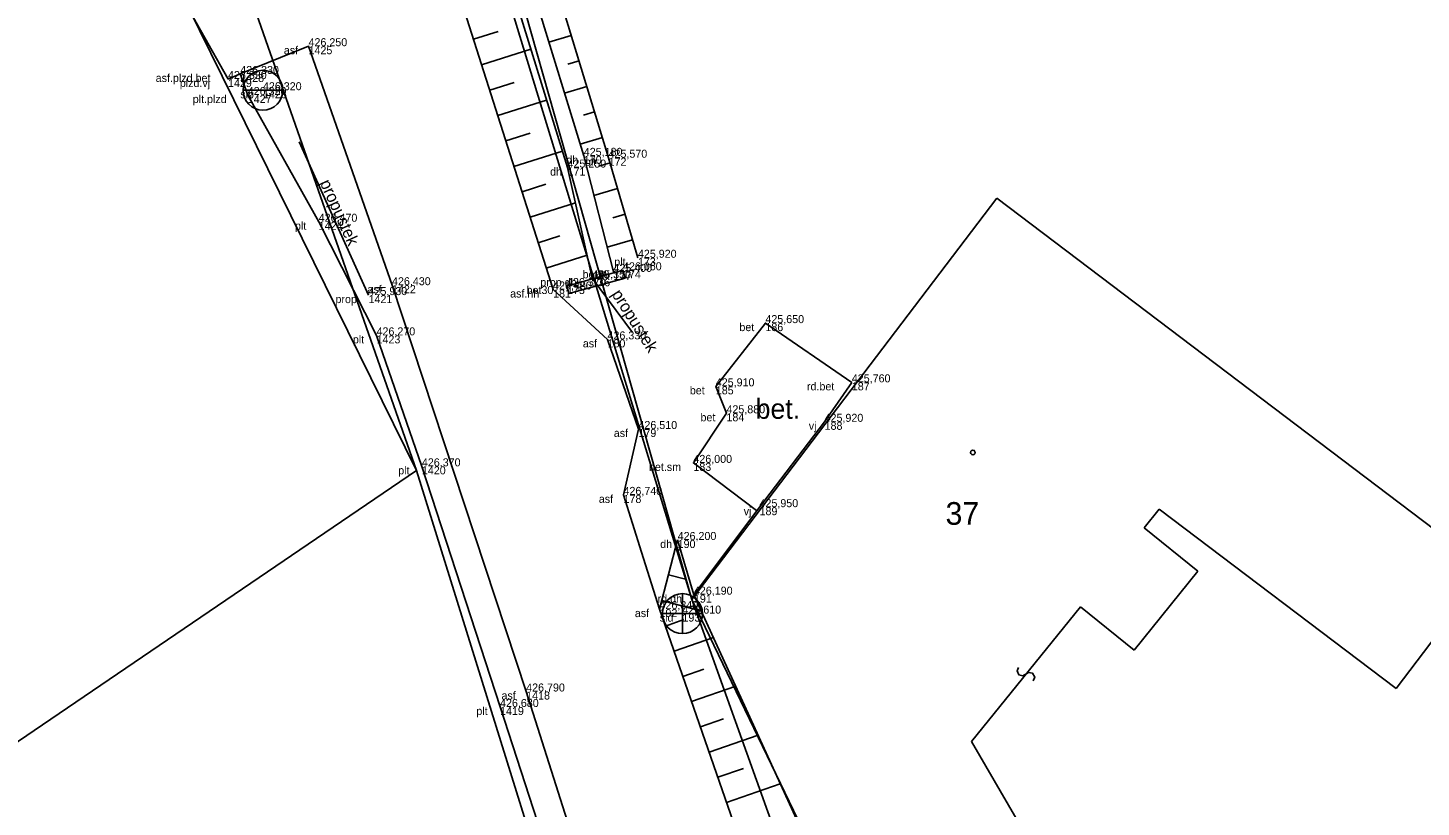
# Model space of a CAD drawing. Extents: x -747792 to -745414, y -1093712 to -1091463.
# Drawn here: x -746629.9 to -746577.7, y -1092879.6 to -1092850.4 of the extents above; entities that cross this region are included whole.
import ezdxf

# ---------------------------------------------------------------- set-up
doc = ezdxf.new("R2010")
doc.units = 0
for name, color, linetype in [('Hladina', 7, 'Continuous'), ('Koleje_dopravní prvky', 7, 'Continuous'), ('Kultury', 7, 'Continuous'), ('Nezařazené objekty', 7, 'Continuous'), ('Nivelační značky_hrany', 7, 'Continuous'), ('Ploty_opěrné zdi', 7, 'Continuous'), ('Popisy objektů_povrchů', 7, 'Continuous'), ('Pracovní_bod PPBP', 7, 'Continuous'), ('Pracovní_bod PPBP - výška', 7, 'Continuous'), ('Pracovní_bod ZPBP', 7, 'Continuous'), ('Pracovní_bod ZPBP - číslo', 7, 'Continuous'), ('Rozhraní ploch', 7, 'Continuous'), ('Stromy_porost', 7, 'Continuous'), ('Výškopis', 7, 'Continuous'), ('Čísla popisná_parcelní', 7, 'Continuous')]:
    doc.layers.add(name, color=color, linetype=linetype)

msp = doc.modelspace()

# ---------------------------------------------------------------- linework, layer by layer
at = {"layer": 'Hladina'}
for p, q in [((-746619.38, -1092851.1), (-746619.38, -1092851.1)), ((-746621.94, -1092852.14), (-746621.94, -1092852.14)), ((-746622.4, -1092852.33), (-746622.4, -1092852.33)), ((-746621.09, -1092852.75), (-746621.09, -1092852.75)), ((-746621.66, -1092852.93), (-746621.66, -1092852.93)), ((-746609.06, -1092855.21), (-746609.06, -1092855.21)), ((-746608.13, -1092855.28), (-746608.13, -1092855.28)), ((-746609.67, -1092855.65), (-746609.67, -1092855.65)), ((-746619, -1092857.68), (-746619, -1092857.68)), ((-746607.03, -1092859.03), (-746607.03, -1092859.03)), ((-746607.95, -1092859.56), (-746607.95, -1092859.56)), ((-746607.59, -1092859.5), (-746607.59, -1092859.5)), ((-746616.25, -1092860.06), (-746616.25, -1092860.06)), ((-746609.69, -1092860.09), (-746609.69, -1092860.09)), ((-746608.74, -1092859.8), (-746608.74, -1092859.8)), ((-746617.13, -1092860.43), (-746617.13, -1092860.43)), ((-746610.21, -1092860.22), (-746610.21, -1092860.22)), ((-746602.25, -1092861.48), (-746602.25, -1092861.48)), ((-746616.83, -1092861.94), (-746616.83, -1092861.94)), ((-746608.17, -1092862.09), (-746608.17, -1092862.09)), ((-746599.01, -1092863.7), (-746599.01, -1092863.7)), ((-746604.11, -1092863.85), (-746604.11, -1092863.85)), ((-746603.71, -1092864.86), (-746603.71, -1092864.86)), ((-746600.03, -1092865.18), (-746600.03, -1092865.18)), ((-746607.01, -1092865.45), (-746607.01, -1092865.45)), ((-746615.13, -1092866.85), (-746615.13, -1092866.85)), ((-746604.95, -1092866.72), (-746604.95, -1092866.72)), ((-746607.57, -1092867.92), (-746607.57, -1092867.92)), ((-746602.47, -1092868.38), (-746602.47, -1092868.38)), ((-746605.54, -1092869.61), (-746605.54, -1092869.61)), ((-746604.93, -1092871.66), (-746604.93, -1092871.66)), ((-746606.22, -1092872.2), (-746606.22, -1092872.2)), ((-746605.36, -1092872.37), (-746605.36, -1092872.37)), ((-746611.22, -1092875.29), (-746611.22, -1092875.29)), ((-746612.2, -1092875.87), (-746612.2, -1092875.87))]:
    msp.add_line(p, q, dxfattribs=at)
at = {"layer": 'Kultury'}
for points in [[(-746587.49, -1092868.45), (-746588.05, -1092869.15)], [(-746578.6, -1092875.18), (-746587.49, -1092868.45)], [(-746586.03, -1092870.78), (-746588.05, -1092869.15)], [(-746588.42, -1092873.74), (-746586.03, -1092870.78)], [(-746590.44, -1092872.11), (-746594.52, -1092877.17)], [(-746590.44, -1092872.11), (-746588.42, -1092873.74)], [(-746578.6, -1092875.18), (-746576.79, -1092872.79)], [(-746592.204, -1092874.895), (-746592.149, -1092874.747), (-746592.232, -1092874.603), (-746592.381, -1092874.572), (-746592.597, -1092874.706), (-746592.744, -1092874.665), (-746592.813, -1092874.519), (-746592.756, -1092874.385)], [(-746580.37, -1092901.51), (-746594.52, -1092877.17)]]:
    msp.add_lwpolyline(points, dxfattribs=at)
at = {"layer": 'Nezařazené objekty'}
for points in [[(-746615.54, -1092831.62), (-746612.94, -1092839.49), (-746608.13, -1092855.28), (-746607.03, -1092859.03)], [(-746621.66, -1092852.93), (-746621.94, -1092852.14), (-746622.4, -1092852.33)], [(-746605.5, -1092896.5), (-746612.2, -1092875.87), (-746615.13, -1092866.85), (-746616.83, -1092861.94), (-746619, -1092857.68), (-746621.66, -1092852.93)]]:
    msp.add_lwpolyline(points, dxfattribs=at)
at = {"layer": 'Nivelační značky_hrany'}
for points in [[(-746618.84, -1092832.7), (-746614.69, -1092846.13), (-746610.21, -1092860.22)], [(-746604.94, -1092923.82), (-746603.73, -1092922.94), (-746602.98, -1092921.58), (-746602.37, -1092919.14), (-746601.93, -1092916.74), (-746601.75, -1092914.6), (-746601.83, -1092911.07), (-746602.53, -1092905.39), (-746603.47, -1092900.25), (-746604.79, -1092895.49), (-746611.22, -1092875.29), (-746616.25, -1092860.06), (-746619.38, -1092851.1), (-746621.94, -1092852.14)], [(-746609.69, -1092860.09), (-746607.59, -1092859.5), (-746607.51, -1092859.789), (-746609.62, -1092860.37), (-746609.69, -1092860.09)], [(-746610.21, -1092860.22), (-746608.17, -1092862.09), (-746607.01, -1092865.45), (-746607.57, -1092867.92), (-746606.89, -1092870.07)], [(-746599.01, -1092863.7), (-746602.25, -1092861.48), (-746604.11, -1092863.85), (-746603.71, -1092864.86), (-746604.95, -1092866.72), (-746602.58, -1092868.51)], [(-746606.89, -1092870.07), (-746606.22, -1092872.2), (-746601.94, -1092884.53), (-746599.63, -1092891.7), (-746597.35, -1092899.83), (-746595.6, -1092905.67), (-746593.1, -1092909.17), (-746589.17, -1092912.29), (-746583.92, -1092914.8), (-746581.66, -1092915.56), (-746580.14, -1092915.86), (-746577.29, -1092915.71), (-746575.17, -1092914.86), (-746572.81, -1092912.41), (-746569.47, -1092912.97), (-746567.46, -1092919.83), (-746565.22, -1092924.53), (-746564.79, -1092924.01)]]:
    msp.add_lwpolyline(points, dxfattribs=at)
at = {"layer": 'Ploty_opěrné zdi'}
msp.add_lwpolyline([(-746594.47, -1092866.245), (-746594.42, -1092866.255), (-746594.395, -1092866.3), (-746594.385, -1092866.33), (-746594.395, -1092866.375), (-746594.435, -1092866.41), (-746594.47, -1092866.415), (-746594.515, -1092866.4), (-746594.545, -1092866.37), (-746594.555, -1092866.33), (-746594.545, -1092866.285), (-746594.505, -1092866.25)], close=True, dxfattribs=at)
at = {"layer": 'Popisy objektů_povrchů'}
for points in [[(-746599.01, -1092863.7), (-746600.03, -1092865.18)], [(-746602.47, -1092868.38), (-746600.03, -1092865.18)], [(-746602.47, -1092868.38), (-746604.93, -1092871.66), (-746599.59, -1092883.35), (-746595.82, -1092889.24)]]:
    msp.add_lwpolyline(points, dxfattribs=at)
at = {"layer": 'Pracovní_bod PPBP'}
for points in [[(-746607.95, -1092859.56), (-746609.06, -1092855.21), (-746612.68, -1092843.4), (-746616.204, -1092831.845)], [(-746617.084, -1092832.121), (-746613.3, -1092843.93), (-746609.67, -1092855.65), (-746608.74, -1092859.8)], [(-746613.192, -1092850.841), (-746612.267, -1092850.547)], [(-746609.527, -1092850.693), (-746610.366, -1092850.949)], [(-746612.889, -1092851.794), (-746611.046, -1092851.208)], [(-746609.236, -1092851.65), (-746609.654, -1092851.777)], [(-746612.586, -1092852.747), (-746611.668, -1092852.455)], [(-746608.944, -1092852.607), (-746609.78, -1092852.861)], [(-746612.283, -1092853.7), (-746610.454, -1092853.118)], [(-746608.653, -1092853.563), (-746609.07, -1092853.69)], [(-746611.98, -1092854.653), (-746611.069, -1092854.363)], [(-746608.362, -1092854.52), (-746609.194, -1092854.773)], [(-746611.677, -1092855.606), (-746609.862, -1092855.029)], [(-746608.072, -1092855.477), (-746608.5, -1092855.602)], [(-746611.374, -1092856.559), (-746610.484, -1092856.276)], [(-746607.791, -1092856.437), (-746608.68, -1092856.698)], [(-746611.071, -1092857.512), (-746609.374, -1092856.972)], [(-746607.509, -1092857.396), (-746607.971, -1092857.532)], [(-746610.768, -1092858.465), (-746609.961, -1092858.208)], [(-746607.228, -1092858.356), (-746608.186, -1092858.637)], [(-746610.465, -1092859.418), (-746608.935, -1092858.931)], [(-746606.22, -1092872.2), (-746605.54, -1092869.61)], [(-746605.629, -1092869.949), (-746605.449, -1092869.996)], [(-746604.93, -1092871.66), (-746605.54, -1092869.61)], [(-746605.883, -1092870.916), (-746605.252, -1092871.082)], [(-746606.137, -1092871.883), (-746604.65, -1092872.274)], [(-746605.999, -1092872.835), (-746605.306, -1092872.595)], [(-746605.672, -1092873.78), (-746604.196, -1092873.268)], [(-746605.344, -1092874.725), (-746604.561, -1092874.453)], [(-746605.016, -1092875.669), (-746603.361, -1092875.095)], [(-746604.688, -1092876.614), (-746603.816, -1092876.311)], [(-746604.36, -1092877.559), (-746602.526, -1092876.922)], [(-746604.032, -1092878.503), (-746603.07, -1092878.17)], [(-746603.704, -1092879.448), (-746601.691, -1092878.75)]]:
    msp.add_lwpolyline(points, dxfattribs=at)
at = {"layer": 'Pracovní_bod PPBP - výška'}
msp.add_lwpolyline([(-746622.4, -1092852.33), (-746624.3, -1092848.94)], dxfattribs=at)
at = {"layer": 'Pracovní_bod ZPBP'}
for points in [[(-746617.13, -1092860.43), (-746619.73, -1092854.69)], [(-746608.74, -1092859.8), (-746607.23, -1092861.83)]]:
    msp.add_lwpolyline(points, dxfattribs=at)
at = {"layer": 'Stromy_porost'}
for points in [[(-746605.01, -1092871.84), (-746616.4, -1092831.67)], [(-746624.42, -1092841.06), (-746615.33, -1092867)], [(-746615.33, -1092867), (-746627.76, -1092841.79)], [(-746613.27, -1092844.77), (-746605.01, -1092871.84)], [(-746593.57, -1092856.8), (-746605.01, -1092871.84)], [(-746575.86, -1092870.2), (-746593.57, -1092856.8)], [(-746663.9, -1092900.02), (-746615.33, -1092867)], [(-746615.33, -1092867), (-746604.26, -1092902.58)], [(-746605.01, -1092871.84), (-746600.2, -1092881.82)], [(-746605.01, -1092871.84), (-746593.18, -1092904.87)]]:
    msp.add_lwpolyline(points, dxfattribs=at)
at = {"layer": 'Čísla popisná_parcelní'}
for p, q in [((-746620.343, -1092852.75), (-746621.838, -1092852.75)), ((-746605.359, -1092871.622), (-746605.36, -1092873.117)), ((-746606.112, -1092872.364), (-746604.612, -1092872.369))]:
    msp.add_line(p, q, dxfattribs=at)
msp.add_circle((-746605.36, -1092872.37), 0.75, dxfattribs=at)
for start, end in [(0, 180), (180, 0)]:
    msp.add_arc((-746621.09, -1092852.75), 0.747, start, end, dxfattribs=at)

# ---------------------------------------------------------------- texts
at = {"layer": 'Koleje_dopravní prvky'}
msp.add_text('37', height=0.85, dxfattribs=at).set_placement((-746595.496, -1092869.04))
at = {"layer": 'Pracovní_bod ZPBP - číslo'}
for s, height, rotation, p in [('propustek', 0.45, 294.4001, (-746618.969, -1092856.215)), ('propustek', 0.45, 302.2556, (-746608.034, -1092860.391)), ('bet.', 0.75, 0.0053, (-746602.617, -1092865.067))]:
    msp.add_text(s, height=height, rotation=rotation, dxfattribs=at).set_placement(p)
at = {"layer": 'Rozhraní ploch'}
for s, p in [(' asf', (-746620.417, -1092851.4)), ('1425', (-746619.38, -1092851.4)), (' asf.plzd.bet', (-746625.223, -1092852.44)), ('1428', (-746621.94, -1092852.44)), (' plzd.vj', (-746624.318, -1092852.63)), ('1429', (-746622.4, -1092852.63)), (' slb', (-746622.051, -1092853.05)), ('1426', (-746621.09, -1092853.05)), (' plt.plzd', (-746623.833, -1092853.23)), ('1427', (-746621.66, -1092853.23)), (' dh', (-746609.825, -1092855.51)), ('170', (-746609.06, -1092855.51)), (' plt', (-746609.129, -1092855.58)), ('172', (-746608.13, -1092855.58)), (' dh', (-746610.435, -1092855.95)), ('171', (-746609.67, -1092855.95)), (' plt', (-746619.999, -1092857.98)), ('1424', (-746619, -1092857.98)), (' plt', (-746608.029, -1092859.33)), ('173', (-746607.03, -1092859.33)), (' bet30', (-746609.217, -1092859.8)), (' dh', (-746608.715, -1092859.86)), ('177', (-746607.95, -1092859.86)), ('174', (-746607.59, -1092859.8)), (' asf', (-746617.287, -1092860.36)), ('1422', (-746616.25, -1092860.36)), (' bet30', (-746611.317, -1092860.39)), (' prop.dh', (-746610.802, -1092860.1)), ('175', (-746609.69, -1092860.39)), ('176', (-746608.74, -1092860.1)), (' prop', (-746618.481, -1092860.73)), ('1421', (-746617.13, -1092860.73)), (' asf.hh', (-746611.932, -1092860.52)), ('181', (-746610.21, -1092860.52)), (' bet', (-746603.336, -1092861.78)), ('186', (-746602.25, -1092861.78)), (' plt', (-746617.829, -1092862.24)), ('1423', (-746616.83, -1092862.24)), (' asf', (-746609.207, -1092862.39)), ('180', (-746608.17, -1092862.39)), (' rd.bet', (-746600.803, -1092864)), ('187', (-746599.01, -1092864)), (' bet', (-746605.196, -1092864.15)), ('185', (-746604.11, -1092864.15)), (' bet', (-746604.796, -1092865.16)), ('184', (-746603.71, -1092865.16)), (' vj', (-746600.734, -1092865.48)), ('188', (-746600.03, -1092865.48)), (' asf', (-746608.047, -1092865.75)), ('179', (-746607.01, -1092865.75)), (' plt', (-746616.129, -1092867.15)), ('1420', (-746615.13, -1092867.15)), (' bet.sm', (-746606.726, -1092867.02)), ('183', (-746604.95, -1092867.02)), (' asf', (-746608.607, -1092868.22)), ('178', (-746607.57, -1092868.22)), (' vj', (-746603.174, -1092868.68)), ('189', (-746602.47, -1092868.68)), (' dh', (-746606.305, -1092869.91)), ('190', (-746605.54, -1092869.91)), (' rd.dh', (-746606.401, -1092871.96)), ('191', (-746604.93, -1092871.96)), (' asf', (-746607.257, -1092872.5)), (' sld', (-746606.321, -1092872.67)), ('192', (-746606.22, -1092872.5)), ('193', (-746605.36, -1092872.67)), (' asf', (-746612.257, -1092875.59)), ('1418', (-746611.22, -1092875.59)), (' plt', (-746613.199, -1092876.17)), ('1419', (-746612.2, -1092876.17))]:
    msp.add_text(s, height=0.3, dxfattribs=at).set_placement(p)
at = {"layer": 'Výškopis'}
for s, p in [('426,250', (-746619.38, -1092851.1)), ('426,330', (-746622.4, -1092852.33)), ('426,330', (-746621.94, -1092852.14)), ('426,320', (-746621.66, -1092852.93)), ('426,320', (-746621.09, -1092852.75)), ('425,250', (-746609.67, -1092855.65)), ('425,180', (-746609.06, -1092855.21)), ('425,570', (-746608.13, -1092855.28)), ('426,470', (-746619, -1092857.68)), ('425,920', (-746607.03, -1092859.03)), ('425,350', (-746608.74, -1092859.8)), ('425,400', (-746607.95, -1092859.56)), ('426,060', (-746607.59, -1092859.5)), ('426,430', (-746616.25, -1092860.06)), ('426,480', (-746610.21, -1092860.22)), ('426,370', (-746609.69, -1092860.09)), ('425,930', (-746617.13, -1092860.43)), ('426,270', (-746616.83, -1092861.94)), ('425,650', (-746602.25, -1092861.48)), ('426,330', (-746608.17, -1092862.09)), ('425,910', (-746604.11, -1092863.85)), ('425,760', (-746599.01, -1092863.7)), ('425,880', (-746603.71, -1092864.86)), ('426,510', (-746607.01, -1092865.45)), ('425,920', (-746600.03, -1092865.18)), ('426,370', (-746615.13, -1092866.85)), ('426,000', (-746604.95, -1092866.72)), ('426,740', (-746607.57, -1092867.92)), ('425,950', (-746602.47, -1092868.38)), ('426,200', (-746605.54, -1092869.61)), ('426,190', (-746604.93, -1092871.66)), ('426,840', (-746606.22, -1092872.2)), ('426,610', (-746605.36, -1092872.37)), ('426,790', (-746611.22, -1092875.29)), ('426,680', (-746612.2, -1092875.87))]:
    msp.add_text(s, height=0.3, dxfattribs=at).set_placement(p)

doc.saveas('drawing.dxf')
